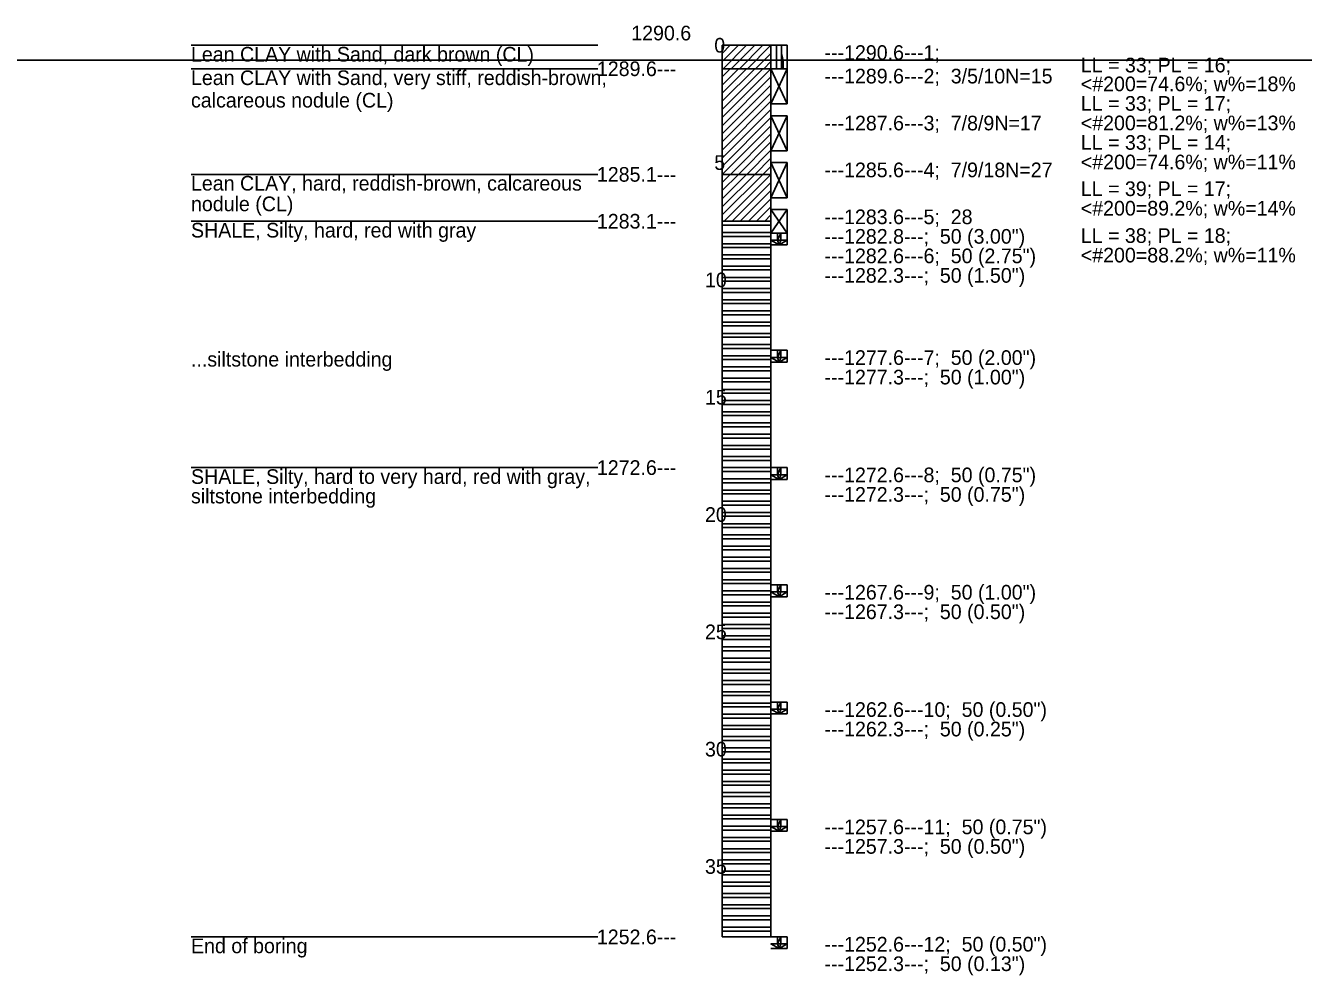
# Model space of a CAD drawing. Extents: x 2150148.6 to 2150220.1, y 143803.7 to 143875.1.
# Drawn here: x 2150182.61 to 2150195.7, y 143849.71 to 143859.44 of the extents above; entities that cross this region are included whole.
import ezdxf

# ---------------------------------------------------------------- set-up
doc = ezdxf.new("R2010")
doc.units = 0
doc.layers.add('Default', color=7, linetype='Continuous')

# ---------------------------------------------------------------- blocks, each defined once
blk = doc.blocks.new('POINT_DISPLAY')
at = {"layer": 'Default'}
blk.add_line((0, 0), (0, 0), dxfattribs=at)

msp = doc.modelspace()

# ---------------------------------------------------------------- linework, layer by layer
at = {"layer": 'Default'}
for points in [[(2150184.309, 143859.238), (2150188.476, 143859.238)], [(2150189.749, 143859.154), (2150189.832, 143859.238)], [(2150189.749, 143859.071), (2150189.916, 143859.238)], [(2150189.749, 143859.238), (2150189.749, 143850.103)], [(2150189.749, 143859.238), (2150190.249, 143859.238)], [(2150189.758, 143858.997), (2150189.999, 143859.238)], [(2150189.842, 143858.997), (2150190.082, 143859.238)], [(2150189.925, 143858.997), (2150190.166, 143859.238)], [(2150190.008, 143858.997), (2150190.249, 143859.238)], [(2150190.092, 143858.997), (2150190.249, 143859.154)], [(2150190.249, 143859.238), (2150190.416, 143859.238)], [(2150190.249, 143859.238), (2150190.249, 143850.103)], [(2150190.416, 143858.997), (2150190.416, 143859.238)], [(2150190.175, 143858.997), (2150190.249, 143859.071)], [(2150184.309, 143858.997), (2150188.476, 143858.997)], [(2150189.749, 143858.997), (2150190.249, 143858.997)], [(2150189.749, 143858.914), (2150189.832, 143858.997)], [(2150189.749, 143858.83), (2150189.916, 143858.997)], [(2150189.749, 143858.747), (2150189.999, 143858.997)], [(2150189.749, 143858.664), (2150190.082, 143858.997)], [(2150189.749, 143858.58), (2150190.166, 143858.997)], [(2150189.749, 143858.497), (2150190.249, 143858.997)], [(2150189.749, 143858.414), (2150190.249, 143858.914)], [(2150190.249, 143858.997), (2150190.416, 143858.997)], [(2150190.249, 143858.997), (2150190.416, 143858.637)], [(2150190.249, 143858.637), (2150190.416, 143858.997)], [(2150190.249, 143858.997), (2150190.416, 143858.997)], [(2150190.416, 143858.637), (2150190.416, 143858.997)], [(2150189.749, 143858.33), (2150190.249, 143858.83)], [(2150189.749, 143858.247), (2150190.249, 143858.747)], [(2150189.749, 143858.164), (2150190.249, 143858.664)], [(2150190.249, 143858.637), (2150190.416, 143858.637)], [(2150189.749, 143858.08), (2150190.249, 143858.58)], [(2150189.749, 143857.997), (2150190.249, 143858.497)], [(2150190.249, 143858.516), (2150190.416, 143858.156)], [(2150190.249, 143858.156), (2150190.416, 143858.516)], [(2150190.249, 143858.516), (2150190.416, 143858.516)], [(2150190.416, 143858.156), (2150190.416, 143858.516)], [(2150189.75, 143857.915), (2150190.249, 143858.414)], [(2150189.834, 143857.915), (2150190.249, 143858.33)], [(2150189.917, 143857.915), (2150190.249, 143858.247)], [(2150190, 143857.915), (2150190.249, 143858.164)], [(2150190.249, 143858.156), (2150190.416, 143858.156)], [(2150190.084, 143857.915), (2150190.249, 143858.08)], [(2150190.167, 143857.915), (2150190.249, 143857.997)], [(2150190.249, 143858.036), (2150190.416, 143857.675)], [(2150190.249, 143857.675), (2150190.416, 143858.036)], [(2150190.249, 143858.036), (2150190.416, 143858.036)], [(2150190.416, 143857.675), (2150190.416, 143858.036)], [(2150184.309, 143857.915), (2150188.476, 143857.915)], [(2150189.749, 143857.915), (2150190.249, 143857.915)], [(2150189.749, 143857.832), (2150189.832, 143857.915)], [(2150189.749, 143857.749), (2150189.916, 143857.915)], [(2150189.749, 143857.665), (2150189.999, 143857.915)], [(2150189.749, 143857.582), (2150190.082, 143857.915)], [(2150189.749, 143857.499), (2150190.166, 143857.915)], [(2150189.768, 143857.435), (2150190.249, 143857.915)], [(2150189.851, 143857.435), (2150190.249, 143857.832)], [(2150189.935, 143857.435), (2150190.249, 143857.749)], [(2150190.018, 143857.435), (2150190.249, 143857.665)], [(2150190.101, 143857.435), (2150190.249, 143857.582)], [(2150190.249, 143857.675), (2150190.416, 143857.675)], [(2150190.185, 143857.435), (2150190.249, 143857.499)], [(2150190.249, 143857.555), (2150190.416, 143857.314)], [(2150190.249, 143857.314), (2150190.416, 143857.555)], [(2150190.249, 143857.555), (2150190.416, 143857.555)], [(2150190.416, 143857.314), (2150190.416, 143857.555)], [(2150184.309, 143857.435), (2150188.476, 143857.435)], [(2150189.749, 143857.435), (2150190.249, 143857.435)], [(2150189.749, 143857.435), (2150190.249, 143857.435)], [(2150189.749, 143857.395), (2150190.249, 143857.395)], [(2150189.749, 143857.32), (2150190.249, 143857.32)], [(2150190.249, 143857.314), (2150190.416, 143857.314)], [(2150190.249, 143857.314), (2150190.416, 143857.314)], [(2150190.416, 143857.194), (2150190.416, 143857.314)], [(2150189.749, 143857.28), (2150190.249, 143857.28)], [(2150189.749, 143857.205), (2150190.249, 143857.205)], [(2150190.249, 143857.194), (2150190.416, 143857.194)], [(2150189.749, 143857.166), (2150190.249, 143857.166)], [(2150189.749, 143857.09), (2150190.249, 143857.09)], [(2150189.749, 143857.051), (2150190.249, 143857.051)], [(2150189.749, 143856.975), (2150190.249, 143856.975)], [(2150189.749, 143856.936), (2150190.249, 143856.936)], [(2150189.749, 143856.86), (2150190.249, 143856.86)], [(2150189.749, 143856.821), (2150190.249, 143856.821)], [(2150189.749, 143856.746), (2150190.249, 143856.746)], [(2150189.749, 143856.706), (2150190.249, 143856.706)], [(2150189.749, 143856.631), (2150190.249, 143856.631)], [(2150189.749, 143856.591), (2150190.249, 143856.591)], [(2150189.749, 143856.516), (2150190.249, 143856.516)], [(2150189.749, 143856.477), (2150190.249, 143856.477)], [(2150189.749, 143856.401), (2150190.249, 143856.401)], [(2150189.749, 143856.362), (2150190.249, 143856.362)], [(2150189.749, 143856.286), (2150190.249, 143856.286)], [(2150189.749, 143856.247), (2150190.249, 143856.247)], [(2150189.749, 143856.172), (2150190.249, 143856.172)], [(2150189.749, 143856.132), (2150190.249, 143856.132)], [(2150189.749, 143856.057), (2150190.249, 143856.057)], [(2150189.749, 143856.017), (2150190.249, 143856.017)], [(2150190.249, 143856.113), (2150190.416, 143856.113)], [(2150190.416, 143855.992), (2150190.416, 143856.113)], [(2150189.749, 143855.942), (2150190.249, 143855.942)], [(2150189.749, 143855.902), (2150190.249, 143855.902)], [(2150190.249, 143855.992), (2150190.416, 143855.992)], [(2150189.749, 143855.827), (2150190.249, 143855.827)], [(2150189.749, 143855.788), (2150190.249, 143855.788)], [(2150189.749, 143855.712), (2150190.249, 143855.712)], [(2150189.749, 143855.673), (2150190.249, 143855.673)], [(2150189.749, 143855.597), (2150190.249, 143855.597)], [(2150189.749, 143855.558), (2150190.249, 143855.558)], [(2150189.749, 143855.483), (2150190.249, 143855.483)], [(2150189.749, 143855.443), (2150190.249, 143855.443)], [(2150189.749, 143855.368), (2150190.249, 143855.368)], [(2150189.749, 143855.328), (2150190.249, 143855.328)], [(2150189.749, 143855.253), (2150190.249, 143855.253)], [(2150189.749, 143855.214), (2150190.249, 143855.214)], [(2150189.749, 143855.138), (2150190.249, 143855.138)], [(2150189.749, 143855.099), (2150190.249, 143855.099)], [(2150189.749, 143855.023), (2150190.249, 143855.023)], [(2150189.749, 143854.984), (2150190.249, 143854.984)], [(2150184.309, 143854.911), (2150188.476, 143854.911)], [(2150189.749, 143854.911), (2150190.249, 143854.911)], [(2150189.749, 143854.911), (2150190.249, 143854.911)], [(2150189.749, 143854.871), (2150190.249, 143854.871)], [(2150190.249, 143854.911), (2150190.416, 143854.911)], [(2150190.416, 143854.79), (2150190.416, 143854.911)], [(2150189.749, 143854.796), (2150190.249, 143854.796)], [(2150189.749, 143854.756), (2150190.249, 143854.756)], [(2150190.249, 143854.79), (2150190.416, 143854.79)], [(2150189.749, 143854.681), (2150190.249, 143854.681)], [(2150189.749, 143854.642), (2150190.249, 143854.642)], [(2150189.749, 143854.566), (2150190.249, 143854.566)], [(2150189.749, 143854.527), (2150190.249, 143854.527)], [(2150189.749, 143854.451), (2150190.249, 143854.451)], [(2150189.749, 143854.412), (2150190.249, 143854.412)], [(2150189.749, 143854.336), (2150190.249, 143854.336)], [(2150189.749, 143854.297), (2150190.249, 143854.297)], [(2150189.749, 143854.222), (2150190.249, 143854.222)], [(2150189.749, 143854.182), (2150190.249, 143854.182)], [(2150189.749, 143854.107), (2150190.249, 143854.107)], [(2150189.749, 143854.067), (2150190.249, 143854.067)], [(2150189.749, 143853.992), (2150190.249, 143853.992)], [(2150189.749, 143853.953), (2150190.249, 143853.953)], [(2150189.749, 143853.877), (2150190.249, 143853.877)], [(2150189.749, 143853.838), (2150190.249, 143853.838)], [(2150189.749, 143853.762), (2150190.249, 143853.762)], [(2150189.749, 143853.723), (2150190.249, 143853.723)], [(2150189.749, 143853.647), (2150190.249, 143853.647)], [(2150190.249, 143853.709), (2150190.416, 143853.709)], [(2150190.416, 143853.588), (2150190.416, 143853.709)], [(2150189.749, 143853.608), (2150190.249, 143853.608)], [(2150189.749, 143853.533), (2150190.249, 143853.533)], [(2150190.249, 143853.588), (2150190.416, 143853.588)], [(2150189.749, 143853.493), (2150190.249, 143853.493)], [(2150189.749, 143853.418), (2150190.249, 143853.418)], [(2150189.749, 143853.378), (2150190.249, 143853.378)], [(2150189.749, 143853.303), (2150190.249, 143853.303)], [(2150189.749, 143853.264), (2150190.249, 143853.264)], [(2150189.749, 143853.188), (2150190.249, 143853.188)], [(2150189.749, 143853.149), (2150190.249, 143853.149)], [(2150189.749, 143853.073), (2150190.249, 143853.073)], [(2150189.749, 143853.034), (2150190.249, 143853.034)], [(2150189.749, 143852.958), (2150190.249, 143852.958)], [(2150189.749, 143852.919), (2150190.249, 143852.919)], [(2150189.749, 143852.844), (2150190.249, 143852.844)], [(2150189.749, 143852.804), (2150190.249, 143852.804)], [(2150189.749, 143852.729), (2150190.249, 143852.729)], [(2150189.749, 143852.689), (2150190.249, 143852.689)], [(2150189.749, 143852.614), (2150190.249, 143852.614)], [(2150189.749, 143852.575), (2150190.249, 143852.575)], [(2150189.749, 143852.499), (2150190.249, 143852.499)], [(2150190.249, 143852.507), (2150190.416, 143852.507)], [(2150190.416, 143852.387), (2150190.416, 143852.507)], [(2150189.749, 143852.46), (2150190.249, 143852.46)], [(2150189.749, 143852.384), (2150190.249, 143852.384)], [(2150189.749, 143852.345), (2150190.249, 143852.345)], [(2150190.249, 143852.387), (2150190.416, 143852.387)], [(2150189.749, 143852.27), (2150190.249, 143852.27)], [(2150189.749, 143852.23), (2150190.249, 143852.23)], [(2150189.749, 143852.155), (2150190.249, 143852.155)], [(2150189.749, 143852.115), (2150190.249, 143852.115)], [(2150189.749, 143852.04), (2150190.249, 143852.04)], [(2150189.749, 143852), (2150190.249, 143852)], [(2150189.749, 143851.925), (2150190.249, 143851.925)], [(2150189.749, 143851.886), (2150190.249, 143851.886)], [(2150189.749, 143851.81), (2150190.249, 143851.81)], [(2150189.749, 143851.771), (2150190.249, 143851.771)], [(2150189.749, 143851.695), (2150190.249, 143851.695)], [(2150189.749, 143851.656), (2150190.249, 143851.656)], [(2150189.749, 143851.581), (2150190.249, 143851.581)], [(2150189.749, 143851.541), (2150190.249, 143851.541)], [(2150189.749, 143851.466), (2150190.249, 143851.466)], [(2150189.749, 143851.426), (2150190.249, 143851.426)], [(2150189.749, 143851.351), (2150190.249, 143851.351)], [(2150189.749, 143851.312), (2150190.249, 143851.312)], [(2150190.249, 143851.305), (2150190.416, 143851.305)], [(2150190.416, 143851.185), (2150190.416, 143851.305)], [(2150189.749, 143851.236), (2150190.249, 143851.236)], [(2150189.749, 143851.197), (2150190.249, 143851.197)], [(2150190.249, 143851.185), (2150190.416, 143851.185)], [(2150189.749, 143851.121), (2150190.249, 143851.121)], [(2150189.749, 143851.082), (2150190.249, 143851.082)], [(2150189.749, 143851.006), (2150190.249, 143851.006)], [(2150189.749, 143850.967), (2150190.249, 143850.967)], [(2150189.749, 143850.892), (2150190.249, 143850.892)], [(2150189.749, 143850.852), (2150190.249, 143850.852)], [(2150189.749, 143850.777), (2150190.249, 143850.777)], [(2150189.749, 143850.737), (2150190.249, 143850.737)], [(2150189.749, 143850.662), (2150190.249, 143850.662)], [(2150189.749, 143850.623), (2150190.249, 143850.623)], [(2150189.749, 143850.547), (2150190.249, 143850.547)], [(2150189.749, 143850.508), (2150190.249, 143850.508)], [(2150189.749, 143850.432), (2150190.249, 143850.432)], [(2150189.749, 143850.393), (2150190.249, 143850.393)], [(2150189.749, 143850.317), (2150190.249, 143850.317)], [(2150189.749, 143850.278), (2150190.249, 143850.278)], [(2150189.749, 143850.203), (2150190.249, 143850.203)], [(2150189.749, 143850.163), (2150190.249, 143850.163)], [(2150184.309, 143850.103), (2150188.476, 143850.103)], [(2150189.749, 143850.103), (2150190.249, 143850.103)], [(2150190.249, 143850.103), (2150190.416, 143850.103)], [(2150190.249, 143849.983), (2150190.416, 143849.983)], [(2150190.416, 143849.983), (2150190.416, 143850.103)]]:
    msp.add_lwpolyline(points, dxfattribs=at)
for points in [[(2150190.307, 143859.238), (2150190.307, 143858.997), (2150190.357, 143858.997), (2150190.357, 143859.238)], [(2150190.357, 143859.153), (2150190.357, 143858.997), (2150190.372, 143859.071), (2150190.357, 143859.153)], [(2150190.357, 143859.153), (2150190.372, 143859.071), (2150190.366, 143859.113), (2150190.357, 143859.153)], [(2150190.357, 143858.997), (2150190.374, 143859.029), (2150190.372, 143859.071), (2150190.357, 143858.997)], [(2150190.357, 143858.997), (2150190.372, 143858.997), (2150190.374, 143859.029), (2150190.357, 143858.997)], [(2150190.316, 143857.242), (2150190.349, 143857.242), (2150190.349, 143857.314), (2150190.316, 143857.242)], [(2150190.316, 143857.242), (2150190.349, 143857.314), (2150190.316, 143857.314), (2150190.316, 143857.242)], [(2150190.316, 143857.242), (2150190.249, 143857.242), (2150190.332, 143857.194), (2150190.316, 143857.242)], [(2150190.316, 143857.242), (2150190.332, 143857.194), (2150190.349, 143857.242), (2150190.316, 143857.242)], [(2150190.332, 143857.194), (2150190.416, 143857.242), (2150190.349, 143857.242), (2150190.332, 143857.194)], [(2150190.316, 143856.04), (2150190.249, 143856.04), (2150190.332, 143855.992), (2150190.316, 143856.04)], [(2150190.316, 143856.04), (2150190.349, 143856.04), (2150190.349, 143856.113), (2150190.316, 143856.04)], [(2150190.316, 143856.04), (2150190.349, 143856.113), (2150190.316, 143856.113), (2150190.316, 143856.04)], [(2150190.316, 143856.04), (2150190.332, 143855.992), (2150190.349, 143856.04), (2150190.316, 143856.04)], [(2150190.332, 143855.992), (2150190.416, 143856.04), (2150190.349, 143856.04), (2150190.332, 143855.992)], [(2150190.316, 143854.838), (2150190.249, 143854.838), (2150190.332, 143854.79), (2150190.316, 143854.838)], [(2150190.316, 143854.838), (2150190.349, 143854.838), (2150190.349, 143854.911), (2150190.316, 143854.838)], [(2150190.316, 143854.838), (2150190.349, 143854.911), (2150190.316, 143854.911), (2150190.316, 143854.838)], [(2150190.316, 143854.838), (2150190.332, 143854.79), (2150190.349, 143854.838), (2150190.316, 143854.838)], [(2150190.332, 143854.79), (2150190.416, 143854.838), (2150190.349, 143854.838), (2150190.332, 143854.79)], [(2150190.316, 143853.637), (2150190.349, 143853.637), (2150190.349, 143853.709), (2150190.316, 143853.637)], [(2150190.316, 143853.637), (2150190.349, 143853.709), (2150190.316, 143853.709), (2150190.316, 143853.637)], [(2150190.316, 143853.637), (2150190.249, 143853.637), (2150190.332, 143853.588), (2150190.316, 143853.637)], [(2150190.316, 143853.637), (2150190.332, 143853.588), (2150190.349, 143853.637), (2150190.316, 143853.637)], [(2150190.332, 143853.588), (2150190.416, 143853.637), (2150190.349, 143853.637), (2150190.332, 143853.588)], [(2150190.316, 143852.435), (2150190.349, 143852.435), (2150190.349, 143852.507), (2150190.316, 143852.435)], [(2150190.316, 143852.435), (2150190.349, 143852.507), (2150190.316, 143852.507), (2150190.316, 143852.435)], [(2150190.316, 143852.435), (2150190.249, 143852.435), (2150190.332, 143852.387), (2150190.316, 143852.435)], [(2150190.316, 143852.435), (2150190.332, 143852.387), (2150190.349, 143852.435), (2150190.316, 143852.435)], [(2150190.332, 143852.387), (2150190.416, 143852.435), (2150190.349, 143852.435), (2150190.332, 143852.387)], [(2150190.316, 143851.233), (2150190.349, 143851.233), (2150190.349, 143851.305), (2150190.316, 143851.233)], [(2150190.316, 143851.233), (2150190.349, 143851.305), (2150190.316, 143851.305), (2150190.316, 143851.233)], [(2150190.316, 143851.233), (2150190.249, 143851.233), (2150190.332, 143851.185), (2150190.316, 143851.233)], [(2150190.316, 143851.233), (2150190.332, 143851.185), (2150190.349, 143851.233), (2150190.316, 143851.233)], [(2150190.332, 143851.185), (2150190.416, 143851.233), (2150190.349, 143851.233), (2150190.332, 143851.185)], [(2150190.316, 143850.031), (2150190.249, 143850.031), (2150190.332, 143849.983), (2150190.316, 143850.031)], [(2150190.316, 143850.031), (2150190.349, 143850.031), (2150190.349, 143850.103), (2150190.316, 143850.031)], [(2150190.316, 143850.031), (2150190.349, 143850.103), (2150190.316, 143850.103), (2150190.316, 143850.031)], [(2150190.316, 143850.031), (2150190.332, 143849.983), (2150190.349, 143850.031), (2150190.316, 143850.031)], [(2150190.332, 143849.983), (2150190.416, 143850.031), (2150190.349, 143850.031), (2150190.332, 143849.983)]]:
    msp.add_lwpolyline(points, close=True, dxfattribs=at)
at = {"layer": 'Defpoints'}
msp.add_line((2150210.379, 143859.086), (2150168.379, 143859.086), dxfattribs=at)

# ---------------------------------------------------------------- block references
at = {"layer": 'Default', "xscale": 0.39369999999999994, "yscale": 0.3936999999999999}
for p in [(2150189.755, 143859.154), (2150189.788, 143859.221), (2150189.855, 143859.188), (2150189.955, 143859.221), (2150189.978, 143859.157), (2150190.055, 143859.188), (2150190.174, 143859.204), (2150190.221, 143859.154), (2150189.788, 143859.054), (2150189.821, 143859.121), (2150189.888, 143859.088), (2150189.955, 143859.021), (2150190.021, 143859.121), (2150190.038, 143859.045), (2150190.121, 143859.121), (2150190.188, 143859.054), (2150189.755, 143858.914), (2150189.788, 143858.98), (2150189.821, 143858.88), (2150189.855, 143858.947), (2150189.955, 143858.98), (2150189.978, 143858.917), (2150190.021, 143858.88), (2150190.055, 143858.947), (2150190.121, 143858.88), (2150190.174, 143858.964), (2150190.221, 143858.914), (2150189.788, 143858.814), (2150189.821, 143858.747), (2150189.888, 143858.847), (2150189.955, 143858.78), (2150190.038, 143858.805), (2150190.055, 143858.747), (2150190.188, 143858.814), (2150189.755, 143858.68), (2150189.855, 143858.647), (2150189.888, 143858.714), (2150189.921, 143858.614), (2150189.973, 143858.703), (2150190.025, 143858.633), (2150190.088, 143858.647), (2150190.155, 143858.614), (2150190.173, 143858.729), (2150190.221, 143858.68), (2150189.821, 143858.547), (2150189.955, 143858.514), (2150189.988, 143858.58), (2150190.067, 143858.547), (2150190.188, 143858.547), (2150189.755, 143858.48), (2150189.788, 143858.414), (2150189.855, 143858.447), (2150189.988, 143858.38), (2150190.021, 143858.447), (2150190.121, 143858.48), (2150190.188, 143858.414), (2150189.755, 143858.247), (2150189.788, 143858.314), (2150189.855, 143858.28), (2150189.955, 143858.314), (2150189.978, 143858.25), (2150190.055, 143858.28), (2150190.088, 143858.347), (2150190.174, 143858.297), (2150190.221, 143858.247), (2150189.788, 143858.147), (2150189.821, 143858.214), (2150189.888, 143858.18), (2150189.955, 143858.114), (2150190.021, 143858.214), (2150190.038, 143858.138), (2150190.121, 143858.214), (2150190.188, 143858.147), (2150189.755, 143858.014), (2150189.821, 143858.08), (2150189.855, 143857.98), (2150189.888, 143858.047), (2150189.973, 143858.037), (2150190.025, 143857.967), (2150190.055, 143858.08), (2150190.088, 143857.98), (2150190.173, 143858.062), (2150190.221, 143858.014), (2150189.921, 143857.947), (2150190.155, 143857.947)]:
    msp.add_blockref('POINT_DISPLAY', p, dxfattribs=at)

# ---------------------------------------------------------------- texts
at = {"layer": 'Default'}
for s, p in [('1290.6', (2150188.818, 143859.288)), ('0', (2150189.668, 143859.163)), ('Lean CLAY with Sand, dark brown (CL)', (2150184.309, 143859.071)), ('---1290.6---1;', (2150190.797, 143859.088)), ('1289.6---', (2150188.466, 143858.922)), ('LL = 33; PL = 16;', (2150193.422, 143858.96)), ('Lean CLAY with Sand, very stiff, reddish-brown,', (2150184.309, 143858.83)), ('---1289.6---2;  3/5/10N=15', (2150190.797, 143858.847)), ('<#200=74.6%; w%=18%', (2150193.422, 143858.767)), ('calcareous nodule (CL)', (2150184.309, 143858.6)), ('LL = 33; PL = 17;', (2150193.422, 143858.567)), ('---1287.6---3;  7/8/9N=17', (2150190.797, 143858.366)), ('<#200=81.2%; w%=13%', (2150193.422, 143858.367)), ('LL = 33; PL = 14;', (2150193.422, 143858.167)), ('5', (2150189.668, 143857.961)), ('<#200=74.6%; w%=11%', (2150193.422, 143857.967)), ('1285.1---', (2150188.466, 143857.84)), ('---1285.6---4;  7/9/18N=27', (2150190.797, 143857.886)), ('Lean CLAY, hard, reddish-brown, calcareous', (2150184.309, 143857.749)), ('LL = 39; PL = 17;', (2150193.422, 143857.693)), ('nodule (CL)', (2150184.309, 143857.538)), ('<#200=89.2%; w%=14%', (2150193.422, 143857.493)), ('1283.1---', (2150188.466, 143857.36)), ('---1283.6---5;  28', (2150190.797, 143857.405)), ('SHALE, Silty, hard, red with gray', (2150184.309, 143857.268)), ('---1282.8---;  50 (3.00")', (2150190.797, 143857.205)), ('LL = 38; PL = 18;', (2150193.422, 143857.213)), ('---1282.6---6;  50 (2.75")', (2150190.797, 143857.005)), ('<#200=88.2%; w%=11%', (2150193.422, 143857.013)), ('---1282.3---;  50 (1.50")', (2150190.797, 143856.805)), ('10', (2150189.573, 143856.759)), ('...siltstone interbedding', (2150184.309, 143855.946)), ('---1277.6---7;  50 (2.00")', (2150190.797, 143855.963)), ('---1277.3---;  50 (1.00")', (2150190.797, 143855.763)), ('15', (2150189.573, 143855.557)), ('1272.6---', (2150188.466, 143854.836)), ('SHALE, Silty, hard to very hard, red with gray,', (2150184.309, 143854.744)), ('---1272.6---8;  50 (0.75")', (2150190.797, 143854.761)), ('siltstone interbedding', (2150184.309, 143854.544)), ('---1272.3---;  50 (0.75")', (2150190.797, 143854.561)), ('20', (2150189.573, 143854.355)), ('---1267.6---9;  50 (1.00")', (2150190.797, 143853.559)), ('---1267.3---;  50 (0.50")', (2150190.797, 143853.359)), ('25', (2150189.573, 143853.153)), ('---1262.6---10;  50 (0.50")', (2150190.797, 143852.357)), ('---1262.3---;  50 (0.25")', (2150190.797, 143852.157)), ('30', (2150189.573, 143851.951)), ('---1257.6---11;  50 (0.75")', (2150190.797, 143851.155)), ('---1257.3---;  50 (0.50")', (2150190.797, 143850.955)), ('35', (2150189.573, 143850.749)), ('1252.6---', (2150188.466, 143850.028)), ('---1252.6---12;  50 (0.50")', (2150190.797, 143849.953)), ('End of boring', (2150184.309, 143849.936)), ('---1252.3---;  50 (0.13")', (2150190.797, 143849.753))]:
    msp.add_text(s, height=0.15, dxfattribs=at).set_placement(p)

doc.saveas('drawing.dxf')
